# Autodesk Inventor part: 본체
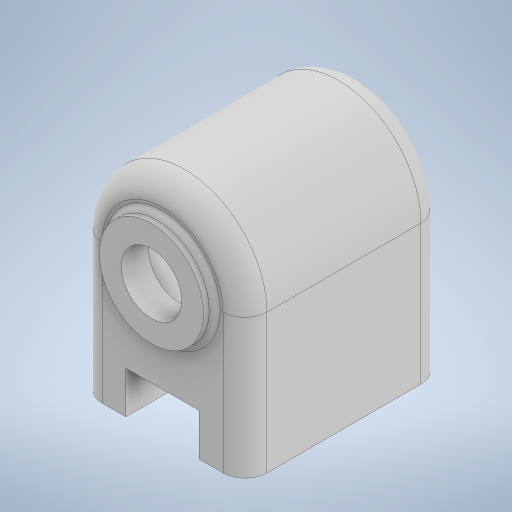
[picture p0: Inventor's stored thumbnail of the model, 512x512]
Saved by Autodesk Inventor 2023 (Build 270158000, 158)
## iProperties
Created: 2024-09
Part Number: 본체
Material: 일반
Document SubType Name: Modeling
Designer: asung
Density: 1 g/cm^3
Appearance: 기본값
Author: asung
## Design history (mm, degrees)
sketch "스케치1"
  geometry: L1 (-45, -38)-(45, -38); L2 (45, -38)-(45, 38); L3 (45, 38)-(-45, 38); L4 (-45, 38)-(-45, -38); L5 (-45, -38)-(45, 38); L6 (45, -38)-(-45, 38); 3 further points
  constraints: 12 end point, 3 midpoint, 2 parallel, 1 horizontal, 1 perpendicular, 3 other
  dimensions: "d0" = 90 distance of L3.end L2.end; "d1" = 76 distance of L2.end L1.end
extrude "돌출1" new body sketch "스케치1" stored distance "d2" = 108; taper "d3" = 0 deg
fillet "모깎기1" dims "d4" = 12
sketch "스케치2"
  geometry: L1 (-45, 38)-(-33, 38) reference; L2 (45, 38)-(33, 38) reference; C1 r 28.5 at (0, 38); A1 r 33 centre (0, 38) between (33, 38) and (-33, 38) reference; A2 r 45 centre (0, 38) between (45, 38) and (-45, 38) reference; 1 further point
  constraints: 1 centre point, 1 coincident
  dimensions: "d5" = 57 diameter of C1
extrude "돌출2" join sketch "스케치2" distance "d6" = 6; taper "d7" = 0 deg
fillet "모깎기2" dims "d8" = 3
sketch "스케치3"
  geometry: L1 (33, 38)-(33, -38) reference; L2 (-33, -38)-(-33, 38) reference; L3 (-33, -38)-(33, -38) reference; L4 (33, -38)-(-33, -38) reference; L5 (-20, -38)-(20, -38); L6 (20, -38)-(20, -15); L7 (20, -15)-(-20, -15); L8 (-20, -15)-(-20, -38); L9 (-45, 38)-(-45, -38) reference; C1 r 31.5 at (0, 38) reference; A1 r 33 centre (0, 38) between (33, 38) and (-33, 38) reference; 3 further points
  constraints: 8 end point, 2 parallel, 1 horizontal, 1 perpendicular, 1 point on line
  dimensions: "d9" = 40 distance of L6.end L7.end; "d10" = 23 distance of L5.end L6.end; "d11" = 25 distance between parallel lines of L9 L8
extrude "돌출3" cut sketch "스케치3" stored distance "d12" = 6; taper "d13" = 0 deg
sketch "스케치5"
  geometry: L1 (69.5, 54)-(71, 54) reference; L2 (83, 42)-(83, -42) reference; L3 (71, -54)-(-15, -54) reference; L4 (-15, -54)-(-15, 54) reference; L5 (-15, 54)-(6.5, 54) reference; L6 (9.5, 57)-(9.5, 60) reference; L7 (9.5, 60)-(66.5, 60) reference; L8 (66.5, 60)-(66.5, 57) reference; L9 (-38, -54)-(38, -54) reference; L10 (38, -54)-(38, 60); L11 (38, -54)-(38, -42) reference; L12 (38, -45)-(71, -45); L13 (74, -42)-(74, 42); L14 (71, 45)-(54.5, 45); L15 (54.5, 45)-(54.5, 60); A1 r 12 centre (71, 42) between (83, 42) and (71, 54) reference; A2 r 12 centre (71, -42) between (71, -54) and (83, -42) reference; A3 r 3 centre (6.5, 57) between (6.5, 54) and (9.5, 57) reference; A4 r 3 centre (69.5, 57) between (66.5, 57) and (69.5, 54) reference; A5 r 3 centre (71, -42) between (71, -45) and (74, -42); A6 r 3 centre (71, 42) between (74, 42) and (71, 45); 2 further points
  constraints: 10 end point, 4 perpendicular, 4 point on circle, 4 tangent, 3 point on line, 2 centre point, 1 equal radius, 1 horizontal, 1 midpoint
  dimensions: "d20" = 9 distance between parallel lines of L3 L12; "d21" = 9 distance between parallel lines of L2 L13; "d22" = 9 distance between parallel lines of L5 L14; "d23" = 33 diameter of L15 L10; "d24" = 3 radius of A5
revolve "회전1" sketch "스케치5" stored, may be unused: angle "d25" = 90 deg
node "솔리드1"
node "투영된 루프1"
node "투영된 루프2"
node "절단 모서리 투영2"
